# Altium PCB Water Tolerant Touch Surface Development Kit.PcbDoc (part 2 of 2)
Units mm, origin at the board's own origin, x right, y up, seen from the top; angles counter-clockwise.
Board outline 95 x 75 mm, 2 copper layers (Top Layer, Bottom Layer); 89 components, 87 nets, 311 pads, 203 vias.
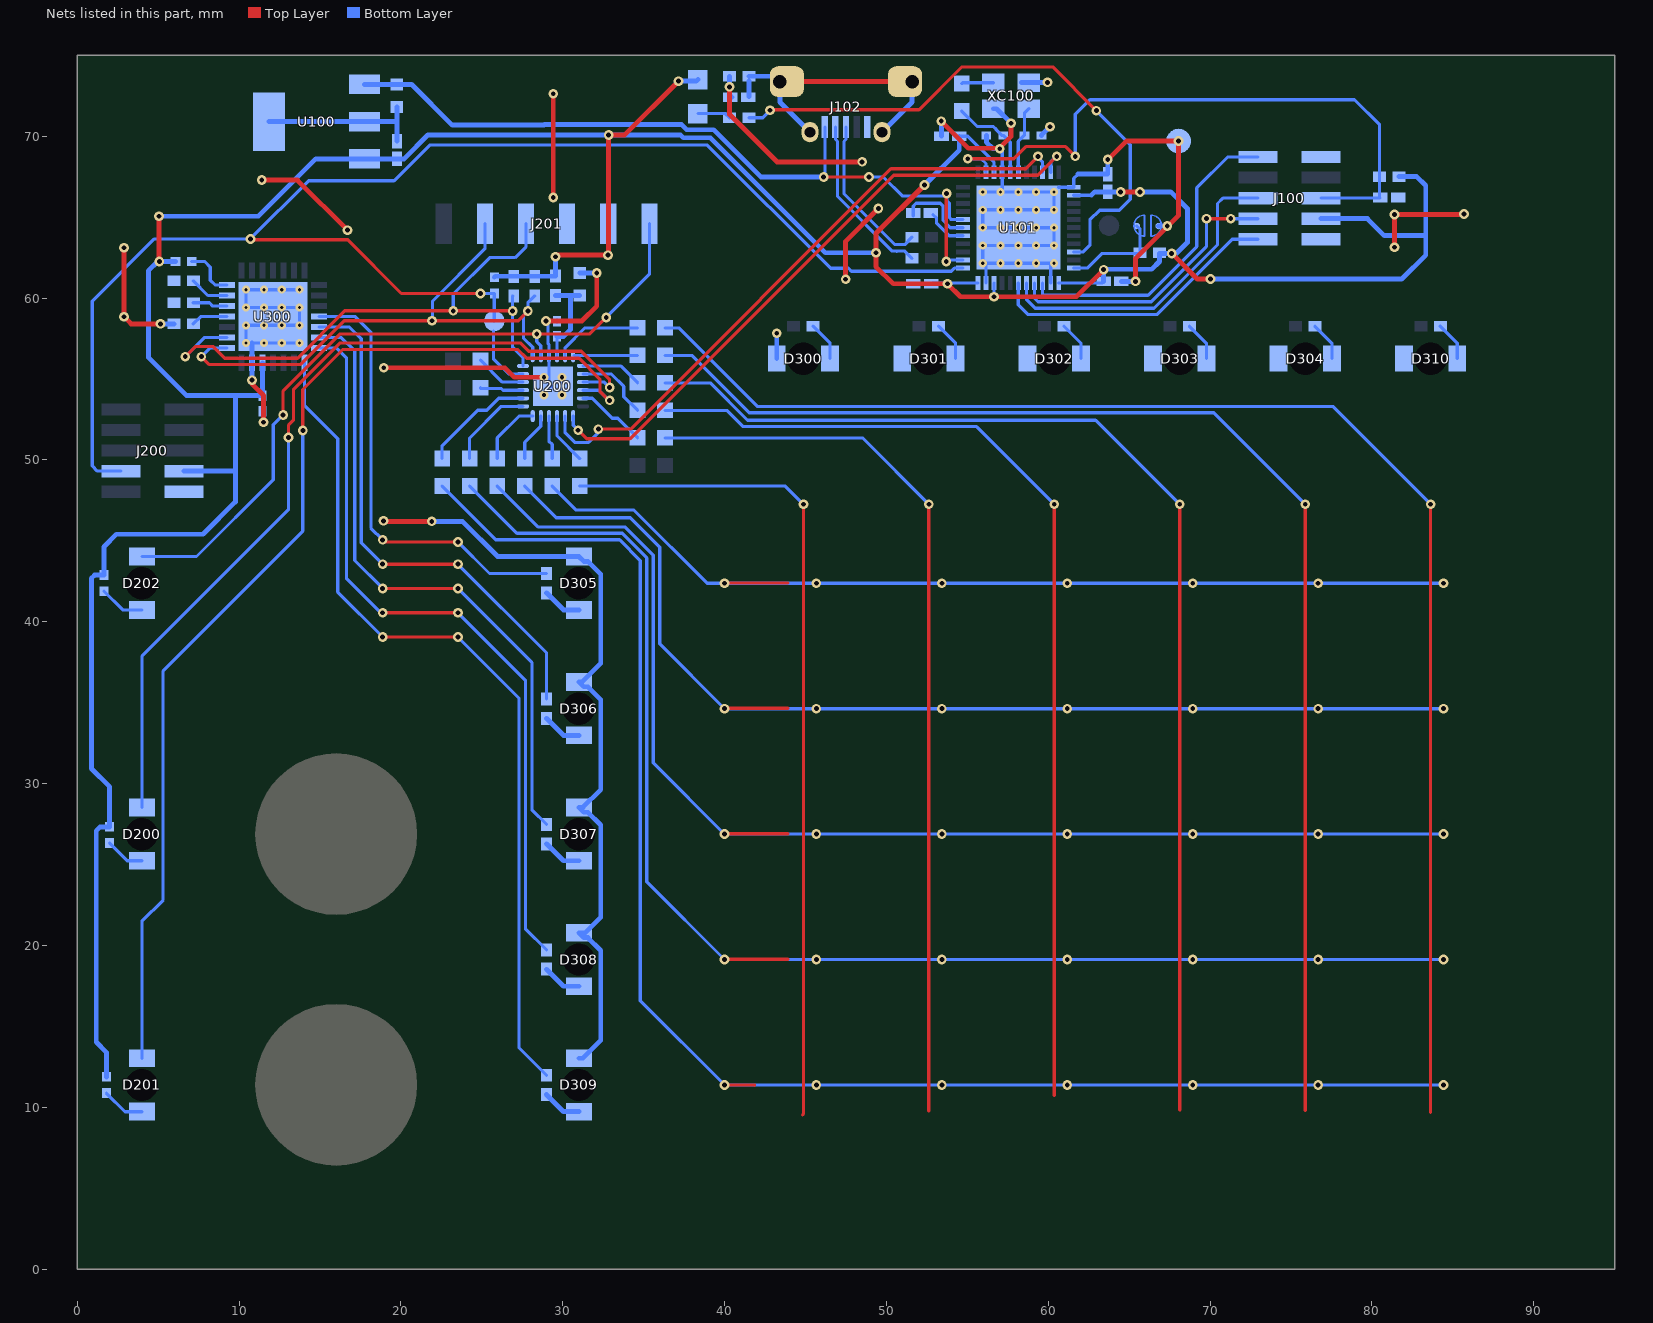
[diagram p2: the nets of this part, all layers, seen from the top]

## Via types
v1: diameter 0.6, hole 0.3, Top Layer to Bottom Layer, 103 vias
v2: diameter 0.6, hole 0.3, Top Layer to Bottom Layer, tented both sides, 55 vias
v3: diameter 0.5, hole 0.2, Top Layer to Bottom Layer, 41 vias
v4: diameter 0.55, hole 0.25, Top Layer to Bottom Layer, 4 vias

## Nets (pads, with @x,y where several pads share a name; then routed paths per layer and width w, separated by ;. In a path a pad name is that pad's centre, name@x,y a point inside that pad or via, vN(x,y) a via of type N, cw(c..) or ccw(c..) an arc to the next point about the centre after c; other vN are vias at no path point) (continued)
GND: C100.2 C101.2 C102.1 C103.1 C104.2 C105.1 C106.1 C107.1 C108.2 C109.1 C110.2 C200.1 C201.1 C300.2 D300.2 D301.2 D302.2 D303.2 D304.2 D305.2 D306.2 D307.2 D308.2 D309.2 D310.2 J100.2 J100.10 J101.1 J102.5 J200.2 J201.3 pad.0 R105.2 R309.1 R311.1 R313.1 U100.2 U100.4 U101.5 U101.15 U101.23 U101.35 U101.43 U101.45 U200.3 U200.25 U300.6 U300.29 XC100.2 XC100.4 | length 216.4
  Top Layer w0.3: v2(2.899,63.105) v2(2.899,58.842) 3.335,58.406 v1(5.15,58.406) ; v1(10.798,54.929) 10.798,54.703 11.516,53.985 v1(11.516,52.325) ; v2(11.403,67.291) 13.611,67.291 v2(16.707,64.195) ; v2(18.929,46.23) 18.96,46.2 v2(21.907,46.2) ; v2(18.941,55.689) 26.43,55.689 27.014,55.105 v4(28.85,55.105) ; v2(28.971,58.58) 31.187,58.58 32.107,59.5 v2(32.107,61.55) ; v2(29.414,66.212) v2(29.414,72.624) ; v2(40.307,73.05) 40.307,71.352 43.243,68.415 v1(48.506,68.415) ; v2(47.485,61.161) 47.485,63.513 v2(49.507,65.534) ; v1(53.391,70.933) 55.068,69.256 56.976,69.256 57.706,69.986 v2(57.706,70.798) ; v1(63.677,68.556) 64.821,69.7 v1(68.057,69.7) 68.057,65.11 65.401,62.455 v1(65.401,61.03) ; v2(81.406,63.142) v2(81.406,65.166) 85.632,65.166 v2@85.693,65.227
  Bottom Layer w0.2: v3(13.74,57.215) 10.795,57.215 v3(10.44,57.215) v3(10.44,58.315) v3(13.74,58.315) v3(13.74,59.415) v3(10.44,59.415) v3(10.44,60.515) v3(13.74,60.515) ; v2(28.971,58.58) C201.1@29.65,58.58 ; v2@29.1,58.355 29.1,57.181 29.15,57.131 U200.3@29.15,56.405 29.15,54.555 U200.25@29.4,54.555 ; D300.2@43.226,56.256 D300.2@43.226,56.256 ; v1(48.506,68.415) v1@48.657,68.565 ; C105.1@52.882,65.15 53.107,64.925 53.107,64.625 53.882,63.85 U101.5@54.732,63.85 ; v3(55.957,66.55) v3(57.057,66.55) ; U101.43@56.157,60.925 U101.45@56.157,62.15 ; v2(57.007,69.225) 57.157,69.075 U101.15@57.157,67.775 57.157,66.65 v3(57.057,66.55) ; U101.35@60.157,60.925 U101.45@60.157,62.15 ; v3(60.357,62.15) v3(55.957,62.15) v3(55.957,63.25) v3(60.357,63.25) v3(60.357,64.35) v3(55.957,64.35) v3(55.957,65.45) v3(60.357,65.45) v3(60.357,66.55) v3(57.057,66.55) ; U101.45@60.657,66.85 U101.23@61.582,66.85 61.582,67.392 61.846,67.656
  Bottom Layer w0.3: v1(5.15,58.406) R309.1@5.977,58.406 ; U300.29@10.795,57.215 10.8,57.21 U300.6@10.8,56.005 10.812,55.993 10.798,55.978 v1(10.798,54.929) ; v3(11.54,58.315) U300.29@11.56,58.315 ; U100.4@11.857,70.9 18.157,70.9 19.707,70.9 19.757,70.85 ; C100.2@19.757,69.7 19.757,70.85 ; C101.2@19.757,71.802 19.757,70.85 ; v2(21.907,46.2) 23.807,46.2 25.977,44.03 D305.2@31,44.03 31.3,43.73 31.559,43.73 32.35,42.939 32.35,37.421 31.207,36.279 D306.2@31,36.279 31.3,35.979 31.559,35.979 32.35,35.188 32.35,29.625 31.253,28.528 D307.2@31,28.528 31.3,28.228 31.559,28.228 32.35,27.437 32.35,21.727 31.4,20.777 D308.2@31,20.777 31.3,20.477 31.559,20.477 32.35,19.686 32.35,14.126 31.25,13.026 D309.2@31,13.026 ; C200.1@31.057,61.548 31.058,61.55 v2(32.107,61.55) ; R105.2@40.307,73.7 v2(40.307,73.05) 40.307,72.555 C106.1@40.457,72.405 ; D300.2@43.226,56.256 v1(43.225,57.826) ; v1(53.391,70.933) 53.407,70.916 C108.2@53.407,70 ; C109.1@56.182,70.05 56.182,69.634 56.591,69.225 v2(57.007,69.225) ; XC100.2@56.607,71.7 56.804,71.7 v2(57.706,70.798) ; XC100.4@58.353,73.325 v1(59.957,73.325) ; C110.2@59.582,70.05 v1(60.112,70.58) ; 61.846,67.656 C107.1@63.677,67.656 v1(63.677,68.556) ; C104.2@64.525,61.03 v1(65.401,61.03) ; J101.1@66.825,64.45 67,64.45 v1(67.357,64.45)
  other v2: 85.693,65.198
  other v3: 11.54,57.215 12.64,57.215 12.64,58.315 11.54,59.415 12.64,59.415 11.54,60.515 12.64,60.515 57.057,62.15 58.157,62.15 59.257,62.15 57.057,63.25 58.157,63.25 59.257,63.25 57.057,64.35 58.157,64.35 59.257,64.35 57.057,65.45 58.157,65.45 59.257,65.45 58.157,66.55 59.257,66.55
  other v4: 28.85,54.005 29.95,54.005 29.95,55.105
NetC105_2: C105.2 U101.6 | length 4.9
  Bottom Layer w0.2: C105.2@51.657,65.075 51.657,65.674 51.833,65.85 53.331,65.85 53.507,65.674 53.507,65.549 53.507,64.791 53.948,64.35 U101.6@54.732,64.35
NetD100_1: D100.1 R101.2 | length 2.1
  Bottom Layer w0.2: D100.1@38.357,71.4 40.052,71.4 R101.2@40.307,71.145
NetD200_1: D200.1 R217.1 | length 2.4
  Bottom Layer w0.2: R217.1@2.007,26.322 3.102,25.227 D200.1@4,25.227
NetD201_1: D201.1 R218.1 | length 2.7
  Bottom Layer w0.2: R218.1@1.807,10.876 2.957,9.726 D201.1@4,9.726
NetD202_1: D202.1 R219.1 | length 2.8
  Bottom Layer w0.2: R219.1@1.657,41.88 2.807,40.73 D202.1@4,40.73
NetD300_1: D300.1 R314.2 | length 2.4
  Bottom Layer w0.2: R314.2@45.476,58.256 46.526,57.206 D300.1@46.526,56.256
NetD301_1: D301.1 R305.2 | length 2.4
  Bottom Layer w0.2: R305.2@53.227,58.256 54.277,57.206 D301.1@54.277,56.256
NetD302_1: D302.1 R304.2 | length 2.4
  Bottom Layer w0.2: R304.2@60.978,58.256 62.028,57.206 D302.1@62.028,56.256
NetD303_1: D303.1 R302.2 | length 2.4
  Bottom Layer w0.2: R302.2@68.729,58.256 69.779,57.206 D303.1@69.779,56.256
NetD304_1: D304.1 R301.2 | length 2.4
  Bottom Layer w0.2: R301.2@76.48,58.256 77.53,57.206 D304.1@77.53,56.256
NetD305_1: D305.1 R306.2 | length 2.4
  Bottom Layer w0.3: R306.2@29,41.78 30.05,40.73 D305.1@31,40.73
NetD306_1: D306.1 R307.2 | length 2.4
  Bottom Layer w0.3: R307.2@29,34.029 30.05,32.979 D306.1@31,32.979
NetD307_1: D307.1 R308.2 | length 2.4
  Bottom Layer w0.3: R308.2@29,26.278 30.05,25.228 D307.1@31,25.228
NetD308_1: D308.1 R310.2 | length 2.4
  Bottom Layer w0.3: R310.2@29,18.527 30.05,17.477 D308.1@31,17.477
NetD309_1: D309.1 R312.2 | length 2.4
  Bottom Layer w0.3: R312.2@29,10.776 30.05,9.726 D309.1@31,9.726
NetD310_1: D310.1 R300.2 | length 2.4
  Bottom Layer w0.2: R300.2@84.231,58.256 85.281,57.206 D310.1@85.281,56.256
NetJ101_2: J101.2 R102.1 U101.33 | length 6.2
  Bottom Layer w0.2: U101.33@61.582,61.85 62.427,61.85 63.333,62.756 R102.1@65.677,62.756 ; J101.2@65.475,64.45 65.677,64.248 65.677,63.885 R102.1@65.677,62.806
NetJ103_1: J103.1 XC100.3 | length 2
  Bottom Layer w0.2: J103.1@54.657,73.25 54.707,73.3 XC100.3@56.607,73.3
NetR303_1: R303.1 U300.14 | length 3.2
  Bottom Layer w0.2: R303.1@7.077,62.256 7.877,62.256 8.227,61.906 8.227,61.106 8.528,60.805 U300.14@9.25,60.805
NetR309_2: R309.2 U300.11 | length 2.3
  Bottom Layer w0.2: R309.2@7.177,58.406 7.626,58.855 U300.11@9.25,58.855
NetR311_2: R311.2 U300.12 | length 2.2
  Bottom Layer w0.2: R311.2@7.177,59.706 8.177,59.706 8.378,59.505 U300.12@9.25,59.505
NetR313_2: R313.2 U300.13 | length 2.4
  Bottom Layer w0.2: R313.2@7.177,61.056 8.078,60.155 U300.13@9.25,60.155
PA0_UPDI_RST: J200.3 R203.1 TP200.1 U101.1 U200.23 | length 95.3
  Top Layer w0.2: v2(10.707,63.65) 10.762,63.595 16.723,63.595 20.037,60.28 v1(24.926,60.28)
  Bottom Layer w0.2: J200.3@2.7,49.305 1.251,49.305 0.925,49.63 0.925,59.804 4.771,63.65 v2(10.707,63.65) 14.307,67.25 19.581,67.25 21.781,69.45 38.939,69.45 46.555,61.834 47.661,61.834 47.839,61.655 54.01,61.655 54.204,61.85 U101.1@54.732,61.85 ; v1(24.926,60.28) R203.1@25.775,60.28 TP200.1@25.775,58.58 ; TP200.1@25.732,57.95 25.732,56.224 26.65,55.305 U200.23@27.55,55.305
PA1_I2C_SDA: J201.4 R202.1 U200.24 U300.9 | length 37.8
  Top Layer w0.2: v1(6.675,56.38) 7.295,57 8.407,57 9.12,56.286 13.619,56.286 16.54,59.207 v2(23.241,59.207) 26.899,59.207 v1(26.907,59.2)
  Bottom Layer w0.2: v1(6.675,56.38) 7.85,57.555 U300.9@9.25,57.555 ; v2(23.241,59.207) 23.241,60.249 25.492,62.5 27.057,62.5 27.737,63.18 J201.4@27.737,64.6 ; R202.1@26.925,60.13 26.907,60.112 v1(26.907,59.2) 26.907,56.949 27.55,56.305 U200.24@27.55,55.805
PA2_I2C_SCL: J201.5 R201.1 U200.1 U300.8 | length 35.4
  Top Layer w0.2: v1(7.675,56.38) 8.169,55.886 13.784,55.886 16.498,58.6 27.256,58.6 v1(27.85,59.195)
  Bottom Layer w0.2: v1(7.675,56.38) 8.2,56.905 U300.8@9.25,56.905 ; v2(21.92,58.6) 21.92,58.713 v2@21.957,58.75 ; v2@21.957,58.55 v2@21.957,58.75 ; J201.5@25.197,64.6 25.197,63.04 21.957,59.8 v2@21.957,58.75 ; U200.1@28.15,56.405 28.15,56.957 27.575,57.532 27.575,58.92 v1(27.85,59.195) 27.85,59.705 R201.1@28.275,60.13
PA3_STATUS_LED_3: D202.2 J201.1 U200.2 | length 46.1
  Top Layer w0.2: v1(12.725,52.775) 12.725,54.261 16.244,57.78 v1(28.399,57.78) 31.673,57.78 v2(32.695,58.802)
  Bottom Layer w0.2: D202.2@4,44.03 7.375,44.03 12.116,48.771 12.116,52.166 v1(12.725,52.775) ; v1(28.399,57.78) 28.399,57.311 28.65,57.059 U200.2@28.65,56.405 ; v2(32.695,58.802) 35.357,61.464 J201.1@35.357,64.6
PB2_UART_TX: U101.20 U200.14 | length 39.1
  Top Layer w0.2: v1(32.207,51.9) 34.198,51.9 50.284,67.986 58.607,67.986 v1(59.377,68.756)
  Bottom Layer w0.2: U200.14@30.15,52.705 30.15,51.676 30.749,51.077 31.599,51.077 32.207,51.685 v1(32.207,51.9) ; v1(59.377,68.756) 59.377,68.682 59.375,68.68 59.657,68.399 U101.20@59.657,67.775
PB3_UART_RX: U101.21 U200.13 | length 39.7
  Top Layer w0.2: v1(30.958,51.83) 31.488,51.3 34.164,51.3 50.449,67.586 59.357,67.586 v1(60.527,68.756)
  Bottom Layer w0.2: 30.657,52.15 30.657,52.699 U200.13@30.65,52.705 30.65,52.137 v1(30.958,51.83) ; U101.21@60.157,67.775 60.157,68.413 60.5,68.756 v1(60.527,68.756)
PB6_LED_2: D201.2 U200.10 | length 69.1
  Top Layer w0.2: v1(13.945,51.816) 13.945,54.349 16.415,56.82 27.229,56.82 27.773,56.276 31.015,56.276 32.3,54.99 32.3,54.229 32.852,53.677 v1(32.9,53.677)
  Bottom Layer w0.2: D201.2@4,13.026 4,21.493 5.307,22.8 5.307,36.962 13.945,45.599 v1(13.945,51.816) ; U200.10@31.25,54.305 32.224,54.305 32.852,53.677 v1(32.9,53.677)
PB7_LED_1: D200.2 U200.9 | length 53.6
  Top Layer w0.2: v1(13.056,51.384) 13.056,52.131 13.36,52.436 13.36,54.331 16.256,57.226 27.388,57.226 27.909,56.705 31.15,56.705 32.9,54.955 v1(32.9,54.477)
  Bottom Layer w0.2: D200.2@4,28.527 4,37.855 13.056,46.91 v1(13.056,51.384) ; U200.9@31.25,54.805 32.572,54.805 v1(32.9,54.477)
ROW_1: R306.1 U300.25 | length 27.7
  Top Layer w0.2: v1(18.877,45.056) 19.003,44.93 v1(23.527,44.93)
  Bottom Layer w0.2: U300.25@14.95,58.855 17.178,58.855 18.15,57.883 18.15,45.783 v1(18.877,45.056) ; v1(23.527,44.93) 25.477,42.98 R306.1@29,42.98
ROW_2: R307.1 U300.26 | length 32.6
  Top Layer w0.2: v1(18.877,43.556) v1(23.527,43.556)
  Bottom Layer w0.2: U300.26@14.95,58.205 16.828,58.205 17.55,57.483 17.55,44.883 v1(18.877,43.556) ; v1(23.527,43.556) 29,38.083 R307.1@29,35.229
ROW_3: R308.1 U300.27 | length 39.4
  Top Layer w0.2: v1(18.877,42.056) v1(23.527,42.056)
  Bottom Layer w0.2: U300.27@14.95,57.555 16.328,57.555 17.15,56.733 17.15,43.783 v1(18.877,42.056) ; v1(23.527,42.056) 28.1,37.483 28.1,28.378 R308.1@29,27.478
ROW_4: R310.1 U300.28 | length 46.4
  Top Layer w0.2: v1(18.877,40.556) v1(23.527,40.556)
  Bottom Layer w0.2: U300.28@14.95,56.905 16.028,56.905 16.65,56.283 16.65,42.657 18.751,40.556 v1(18.877,40.556) ; v1(23.527,40.556) 27.7,36.383 27.7,21.027 R310.1@29,19.727
ROW_5: R312.1 U300.1 | length 52.9
  Top Layer w0.2: v1(18.877,39.056) v1(23.527,39.056)
  Bottom Layer w0.2: U300.1@14.05,56.005 14.05,53.356 16.1,51.306 16.1,41.833 v1(18.877,39.056) ; v1(23.527,39.056) 27.3,35.283 27.3,13.676 R312.1@29,11.976
S\R\S\T\: C102.2 J100.6 R100.1 U101.13 | length 39.6
  Top Layer w0.2: v1(55.027,68.606) 57.877,68.606 58.627,69.356 61.077,69.356 v1(61.677,68.756)
  Bottom Layer w0.2: v1(55.027,68.606) 55.865,68.606 56.157,68.314 U101.13@56.157,67.775 U101.13@56.107,67.825 ; v1(61.677,68.756) 61.677,71.356 62.577,72.256 78.927,72.256 80.477,70.706 R100.1@80.477,67.506 C102.2@80.477,66.256 ; J100.6@76.857,66.175 C102.2@80.496,66.175
SHIELD: C106.2 J102.6@43.419,73.375 J102.7@51.594,73.375 J102.8@45.282,70.25 J102.9@49.732,70.25 R105.1 | length 19.3
  Top Layer w0.3: J102.6@43.419,73.375 J102.7@51.594,73.375
  Bottom Layer w0.3: C106.2@41.507,72.455 R105.1@41.507,73.425 ; R105.1@41.507,73.7 43.094,73.7 J102.6@43.419,73.375 ; J102.6@43.169,73.125 J102.6@43.419,73.375 ; J102.8@45.282,70.25 43.419,72.112 J102.6@43.419,73.375 ; J102.9@49.732,70.25 51.594,72.112 J102.7@51.594,73.375
STATUS_LED: R101.1 U101.31 | length 36
  Top Layer w0.2: v2@42.807,71.63 52.025,71.63 54.675,74.28 60.275,74.28 v1(62.977,71.579)
  Bottom Layer w0.2: R101.1@41.507,71.145 42.371,71.145 42.807,71.58 v2(42.807,71.6) ; U101.31@61.582,62.85 62.171,62.85 62.577,63.256 62.577,64.832 63.175,65.43 64.401,65.43 65.077,66.106 65.077,69.479 v1(62.977,71.579)
TCK: J100.1 U101.39 | length 18.3
  Bottom Layer w0.2: U101.39@58.157,60.925 58.157,59.575 58.757,58.975 66.706,58.975 71.366,63.635 J100.1@72.957,63.635
TDI: J100.9 U101.36 | length 19.7
  Bottom Layer w0.2: U101.36@59.657,60.925 59.657,60.225 59.707,60.175 66.174,60.175 69.178,63.178 69.178,66.807 71.086,68.715 J100.9@72.957,68.715
TDO: J100.3 U101.37 | length 18
  Top Layer w0.2: v1(69.778,64.905) v1(71.278,64.905)
  Bottom Layer w0.2: U101.37@59.157,60.925 59.157,59.991 59.373,59.775 66.374,59.775 69.778,63.178 v1(69.778,64.905) ; v1(71.278,64.905) J100.3@72.957,64.905
TMS: J100.5 U101.38 | length 19.8
  Bottom Layer w0.2: U101.38@58.657,60.925 58.657,59.925 59.207,59.375 66.54,59.375 70.461,63.296 70.461,65.84 70.796,66.175 J100.5@72.957,66.175
USB_VBUS: C101.1 J102.1 U100.1 U101.2 U101.7 | length 49.8
  Top Layer w0.2: v1(46.125,67.476) v1(48.925,67.476) ; v2(53.7,62.255) 53.7,66.429 v1(53.727,66.456)
  Bottom Layer w0.2: v1(46.125,67.476) 46.207,67.557 J102.1@46.207,70.575 ; v1(48.925,67.476) 49.825,67.476 51.001,66.3 53.571,66.3 v1(53.727,66.456) 53.727,66.02 53.907,65.84 53.907,64.956 54.013,64.85 U101.7@54.732,64.85 ; v2(53.7,62.255) 53.794,62.35 U101.2@54.732,62.35
  Bottom Layer w0.3: U100.1@17.757,73.2 17.758,73.198 C101.1@19.757,73.198 20.658,73.198 23.173,70.684 28.838,70.684 28.882,70.729 37.333,70.729 37.662,70.4 39.333,70.4 42.257,67.476 v1(46.125,67.476)
USBD_N: J102.2 R103.1 | length 10.7
  Bottom Layer w0.2: J102.2@46.857,70.575 46.857,69.8 46.982,69.675 46.982,66.285 50.367,62.9 50.641,62.9 50.649,62.892 ; 50.438,62.9 51.132,62.9 R103.1@51.582,62.45
USBD_P: J102.3 R104.1 | length 9.9
  Bottom Layer w0.2: J102.3@47.507,70.575 47.507,69.8 47.382,69.675 47.382,66.451 50.533,63.3 51.132,63.3 R104.1@51.582,63.75
VCC_MCU_P3V3: C200.2 C201.2 R200.2 U200.4 | length 5.8
  Bottom Layer w0.2: U200.4@29.65,56.405 C201.2@29.65,57.63
  Bottom Layer w0.3: R200.2@29.557,60.15 29.558,60.152 30.515,60.152 ; C201.2@29.65,57.63 30.063,57.63 30.475,58.043 30.475,60.112 30.515,60.152 ; C200.2@31.057,60.152 30.515,60.152
VCC_TARGET_P3V3: C100.1 C103.2 C104.1 C107.2 C108.1 C300.1 D100.2 J100.4 J200.4 J201.2 R100.2 R102.2 R200.1 R201.2 R202.2 R203.2 R217.2 R218.2 R219.2 R303.2 U100.3 U101.14 U101.24 U101.34 U101.42 U101.44 U300.5 | length 230.2
  Top Layer w0.3: v1(5.057,65.05) 5.057,62.276 v1(5.077,62.256) ; v2(29.557,62.55) 29.657,62.65 v2(32.807,62.65) 32.842,62.685 v2(32.842,70.079) 33.835,70.079 v2(37.157,73.4) ; v1(52.357,66.986) 49.357,63.986 v1(49.357,62.8) 49.357,61.946 50.422,60.88 v1(53.775,60.88) 54.581,60.075 v1(56.657,60.075) 61.746,60.075 v1(63.425,61.754) ; v1(64.477,66.556) v1(65.677,66.556) ; v1(67.627,62.756) 69.207,61.176 v1(70.025,61.176)
  Bottom Layer w0.2: v1(53.775,60.88) 53.82,60.925 U101.44@55.657,60.925 ; C108.1@54.507,70 55.036,70 56.657,68.379 U101.14@56.657,67.775 ; v1(56.657,60.075) U101.42@56.657,60.925 ; U101.34@60.657,60.925 63.32,60.925 C104.1@63.425,61.03 ; U101.24@61.582,66.35 62.671,66.35
  Bottom Layer w0.3: R218.2@1.807,11.876 1.807,13.399 1.175,14.03 1.175,27.08 1.417,27.322 R217.2@2.007,27.322 2.007,29.799 0.875,30.93 0.875,42.68 1.075,42.88 R219.2@1.657,42.88 1.657,44.636 2.427,45.406 7.777,45.406 9.777,47.406 9.777,49.276 ; v1(5.057,65.05) 11.2,65.05 14.75,68.6 U100.3@17.757,68.6 20.201,68.6 21.679,70.079 37.276,70.079 37.455,69.9 39.126,69.9 46.226,62.8 v1(49.357,62.8) ; R303.2@6.077,62.256 v1(5.077,62.256) 4.977,62.256 4.4,61.679 4.4,56.333 6.752,53.981 9.777,53.981 ; J200.4@6.6,49.305 9.748,49.305 9.777,49.276 ; U300.5@11.45,56.005 11.462,55.992 11.462,54.88 11.45,54.868 11.45,53.981 9.777,53.981 ; R203.2@25.775,61.28 25.845,61.35 R200.1@29.557,61.35 v2(29.557,62.55) ; v2(32.807,62.65) 32.817,62.66 J201.2@32.817,64.6 ; v2(37.157,73.4) 38.257,73.4 D100.2@38.357,73.5 ; v1(52.357,66.986) 54.507,69.136 C108.1@54.507,70 ; C103.2@52.876,60.88 v1(53.775,60.88) ; 62.671,66.35 62.877,66.556 C107.2@63.677,66.556 v1(64.477,66.556) ; C104.1@63.425,61.03 v1(63.425,61.754) 63.451,61.78 66.401,61.78 66.877,62.256 66.877,62.756 v1(67.627,62.756) 67.927,62.756 68.607,63.436 68.607,65.526 67.577,66.556 v1(65.677,66.556) ; v1(70.025,61.176) 81.847,61.176 83.327,62.656 83.327,63.856 ; J100.4@76.857,64.905 79.728,64.905 80.777,63.856 83.327,63.856 ; R100.2@81.677,67.506 82.777,67.506 83.327,66.956 83.327,63.856 ; 9.777,49.276 9.777,53.981
XTAL1: C110.1 U101.17 XC100.1 | length 4.2
  Bottom Layer w0.2: U101.17@58.157,67.775 58.157,69.675 C110.1@58.532,70.05 58.532,71.425 XC100.1@58.807,71.7
XTAL2: C109.2 J103.2 U101.16 | length 5.7
  Bottom Layer w0.2: J103.2@54.657,71.55 55.607,70.6 56.606,70.6 56.782,70.424 56.782,70.401 57.132,70.05 C109.2@57.232,70.05 57.657,69.625 U101.16@57.657,67.775
Y0: R204.1 U200.5 | length 5.5
  Bottom Layer w0.2: U200.5@30.15,56.405 30.15,56.927 31.378,58.155 R204.1@34.625,58.155
Y0_COL6: R204.2 | length 89.4
  Top Layer w0.2: 83.631,9.688 v1(83.631,47.255) v1@83.65,47.236
  Bottom Layer w0.2: R204.2@36.325,58.155 37.17,58.155 42.02,53.305 77.581,53.305 v1(83.631,47.255)
Y1: R210.1 U200.6 | length 3.9
  Bottom Layer w0.2: U200.6@30.7,56.455 R210.1@34.625,56.455
Y1_COL5: R210.2 | length 80.8
  Top Layer w0.2: 75.88,9.811 v1(75.88,47.255)
  Bottom Layer w0.2: R210.2@36.325,56.455 37.985,56.455 41.535,52.905 70.23,52.905 v1(75.88,47.255)
Y2: R211.1 U200.7 | length 3.8
  Bottom Layer w0.2: U200.7@31.25,55.805 33.575,55.805 R211.1@34.625,54.755
Y2_COL4: R211.2 | length 72.3
  Top Layer w0.2: 68.125,9.826 68.129,9.83 v1(68.129,47.255)
  Bottom Layer w0.2: R211.2@36.325,54.755 39.119,54.755 41.419,52.455 62.929,52.455 v1(68.129,47.255)
Y3: R212.1 U200.8 | length 4.7
  Bottom Layer w0.2: U200.8@31.25,55.305 33.01,55.305 33.777,54.539 33.777,54.38 33.777,54.063 33.777,53.904 R212.1@34.625,53.055
Y3_COL3: R212.2 | length 63
  Top Layer w0.2: 60.375,10.726 v1@60.375,47.255
  Bottom Layer w0.2: R212.2@36.325,53.055 40.145,53.055 41.145,52.055 55.578,52.055 v1(60.378,47.255)
Y4: R214.1 U200.15 | length 3.2
  Bottom Layer w0.2: U200.15@29.65,52.705 29.65,51.48 R214.1@31.05,50.08
Y4_COL1: R214.2 | length 52
  Top Layer w0.2: 44.825,9.526 44.876,9.577 v1(44.876,47.255)
  Bottom Layer w0.2: R214.2@31.05,48.38 43.751,48.38 v1(44.876,47.255)
Y5: R209.1 U200.16 | length 2.7
  Bottom Layer w0.2: U200.16@29.15,52.705 29.15,51.156 29.35,50.956 R209.1@29.35,50.08
Y5_ROW5: R209.2 | length 61.4
  Top Layer w0.2: v1@40.019,42.399 43.901,42.399
  Bottom Layer w0.2: R209.2@29.35,48.38 30.83,46.9 34.406,46.9 38.926,42.38 v1(40,42.38) v1(84.432,42.38)
  other v1: 45.677,42.38 53.428,42.38 61.179,42.38 68.93,42.38 76.681,42.38
Y6: R208.1 U200.17 | length 3
  Bottom Layer w0.2: R208.1@27.65,50.08 27.65,51.08 28.65,52.08 U200.17@28.65,52.705
Y6_ROW4: R208.2 | length 69.9
  Top Layer w0.2: v1@40.019,34.648 43.901,34.648
  Bottom Layer w0.2: R208.2@27.65,48.38 29.6,46.43 34.175,46.43 36,44.605 36,38.629 v1(40,34.629) v1(84.432,34.629)
  other v1: 45.677,34.629 53.428,34.629 61.179,34.629 68.93,34.629 76.681,34.629
Y7: R207.1 U200.18 | length 4
  Bottom Layer w0.2: R207.1@25.95,50.08 25.95,51.355 27.3,52.705 U200.18@28.15,52.705
Y7_ROW3: R207.2 | length 78.8
  Top Layer w0.2: v1@40.019,26.897 43.901,26.897
  Bottom Layer w0.2: R207.2@25.95,48.38 28.472,45.859 33.847,45.859 35.6,44.105 35.6,31.278 v1(40,26.878) v1(45.677,26.878) v1(53.428,26.878) v1(61.179,26.878) v1(68.93,26.878) v1(76.681,26.878) v1(84.432,26.878)
Y8: R206.1 U200.19 | length 5.4
  Bottom Layer w0.2: R206.1@24.25,50.08 24.25,51.351 26.205,53.305 U200.19@27.55,53.305
Y8_ROW2: R206.2 | length 87.9
  Top Layer w0.2: v1@40.019,19.146 43.901,19.146
  Bottom Layer w0.2: R206.2@24.25,48.38 27.172,45.459 33.681,45.459 35.2,43.94 35.2,23.927 v1(40,19.127) v1(84.432,19.127)
  other v1: 45.677,19.127 53.428,19.127 61.179,19.127 68.93,19.127 76.681,19.127
Y9: R205.1 U200.20 | length 7
  Bottom Layer w0.2: R205.1@22.55,50.08 22.55,50.871 24.745,53.066 25.31,53.066 26.05,53.805 U200.20@27.55,53.805
Y9_ROW1: R205.2 | length 95
  Top Layer w0.2: v1(40,11.376) 41.831,11.376 41.857,11.35
  Bottom Layer w0.2: R205.2@22.55,48.38 25.872,45.059 33.516,45.059 34.8,43.774 34.8,16.576 v1(40,11.376) v1(45.677,11.376) v1(53.428,11.376) v1(61.179,11.376) v1(68.93,11.376) v1(76.681,11.376) v1(84.432,11.376)
Y10: R215.1 U200.21 | length 2.7
  Bottom Layer w0.2: R215.1@24.925,54.455 24.925,54.405 26.218,54.405 26.318,54.305 U200.21@27.55,54.305
Y11: R216.1 U200.22 | length 3.2
  Bottom Layer w0.2: R216.1@24.925,56.155 26.275,54.805 U200.22@27.55,54.805
Y12: R213.1 U200.11 | length 4.4
  Bottom Layer w0.2: U200.11@31.25,53.805 31.837,53.805 33.065,52.577 33.403,52.577 R213.1@34.625,51.355
Y12_COL2: R213.2 | length 55.5
  Top Layer w0.2: v1(52.627,47.255) 52.625,9.776 52.627,9.778 ; v1(52.627,47.255) v1@52.627,47.296
  Bottom Layer w0.2: R213.2@36.325,51.355 48.527,51.355 v1(52.627,47.255)
pads on no net: D200.0 D201.0 D202.0 D300.0 D301.0 D302.0 D303.0 D304.0 D305.0 D306.0 D307.0 D308.0 D309.0 D310.0 J100.7 J100.8 J102.4 J102.6@43.907,73.375 J102.7@51.107,73.375 J102.8@45.282,70.25 J102.9@49.732,70.25 J200.1 J200.5 J200.6 J200.7 J200.8 J200.9 J200.10 J201.6 U101.8 U101.9 U101.10 U101.11 U101.12 U101.18 U101.19 U101.22 U101.25 U101.26 U101.27 U101.28 U101.29 U101.30 U101.40 U101.41 U300.2 U300.3 U300.4 U300.7 U300.10 U300.15 U300.16 U300.23 U300.24

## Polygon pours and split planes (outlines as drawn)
DRIVEN_SHIELD on Top Layer "DS" (solid, remove dead copper, pour order 12): 2.362,3 92,3 92,57.855 2.362,57.855
DRIVEN_SHIELD on Bottom Layer "DS" (solid, remove dead copper, pour order 14): 5.207,3 92,3 92,50.267 32.156,50.267 32.156,37.836 5.207,37.836
GND on Bottom Layer "Top Layer" (solid, remove dead copper, pour order 10): 19.257,45.6 18.757,45.6 2.184,45.6 2.184,74.15 92,74.15 92,54.839 41.518,54.839 36.857,59.5 35.207,59.5 32.507,59.5 19.257,59.5

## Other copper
Top Layer:
  pour cut-out: 2.172,57.757 2.172,45.555 32.042,45.555 32.332,45.555 32.332,57.757
  pour cut-out: 40.757,7.25 87.757,7.25 87.757,46.5 40.757,46.5
  pour cut-out: 29.85,24.478 29.85,29.278 32.15,29.278 32.15,24.478
  pour cut-out: 29.65,39.78 32.35,39.78 32.35,44.98 29.65,44.98
  pour cut-out: 29.65,32.029 32.35,32.029 32.35,37.229 29.65,37.229
  pour cut-out: 29.65,16.527 32.35,16.527 32.35,21.727 29.65,21.727
  pour cut-out: 29.65,8.776 32.35,8.776 32.35,13.976 29.65,13.976
  region net Y9_ROW1: 52.287,11.376 48.752,14.911 45.216,11.376 48.752,7.84
  region net Y4_COL1: 44.876,18.787 41.34,15.251 44.876,11.716 48.412,15.251
  region net Y4_COL1: 44.876,11.036 48.412,7.5 41.34,7.5
  region net Y9_ROW1: 44.536,11.376 41,7.84 41,14.911
  region net Y12_COL2: 52.627,11.036 56.163,7.5 49.092,7.5
  region net Y12_COL2: 52.627,18.787 49.092,15.251 52.627,11.716 56.163,15.251
  region net Y9_ROW1: 60.038,11.376 56.503,14.911 52.967,11.376 56.503,7.84
  region net Y3_COL3: 60.378,11.036 63.914,7.5 56.843,7.5
  region net Y3_COL3: 60.378,18.787 56.843,15.251 60.378,11.716 63.914,15.251
  region net Y9_ROW1: 67.789,11.376 64.254,14.911 60.718,11.376 64.254,7.84
  region net Y0_COL6: 83.631,18.787 80.096,15.251 83.631,11.716 87.167,15.251
  region net Y0_COL6: 83.631,11.036 87.167,7.5 80.096,7.5
  region net Y9_ROW1: 83.291,11.376 79.756,14.911 76.22,11.376 79.756,7.84
  region net Y1_COL5: 75.88,18.787 72.345,15.251 75.88,11.716 79.416,15.251
  region net Y1_COL5: 75.88,11.036 79.416,7.5 72.345,7.5
  region net Y2_COL4: 68.129,11.036 71.665,7.5 64.594,7.5
  region net Y2_COL4: 68.129,18.787 64.594,15.251 68.129,11.716 71.665,15.251
  region net Y9_ROW1: 75.54,11.376 72.005,14.911 68.469,11.376 72.005,7.84
  region net Y9_ROW1: 83.971,11.376 87.507,14.911 87.507,7.84
  region net Y8_ROW2: 83.971,19.127 87.507,22.662 87.507,15.591
  region net Y8_ROW2: 75.54,19.127 72.005,22.662 68.469,19.127 72.005,15.591
  region net Y2_COL4: 68.129,26.538 64.594,23.002 68.129,19.467 71.665,23.002
  region net Y1_COL5: 75.88,26.538 72.345,23.002 75.88,19.467 79.416,23.002
  region net Y8_ROW2: 83.291,19.127 79.756,22.662 76.22,19.127 79.756,15.591
  region net Y0_COL6: 83.631,26.538 80.096,23.002 83.631,19.467 87.167,23.002
  region net Y8_ROW2: 67.789,19.127 64.254,22.662 60.718,19.127 64.254,15.591
  region net Y3_COL3: 60.378,26.538 56.843,23.002 60.378,19.467 63.914,23.002
  region net Y8_ROW2: 60.038,19.127 56.503,22.662 52.967,19.127 56.503,15.591
  region net Y12_COL2: 52.627,26.538 49.092,23.002 52.627,19.467 56.163,23.002
  region net Y8_ROW2: 44.536,19.127 41,15.591 41,22.662
  region net Y4_COL1: 44.876,26.538 41.34,23.002 44.876,19.467 48.412,23.002
  region net Y8_ROW2: 52.287,19.127 48.752,22.662 45.216,19.127 48.752,15.591
  region net Y7_ROW3: 83.971,26.878 87.507,30.413 87.507,23.342
  region net Y7_ROW3: 75.54,26.878 72.005,30.413 68.469,26.878 72.005,23.342
  region net Y2_COL4: 68.129,34.289 64.594,30.753 68.129,27.218 71.665,30.753
  region net Y1_COL5: 75.88,34.289 72.345,30.753 75.88,27.218 79.416,30.753
  region net Y7_ROW3: 83.291,26.878 79.756,30.413 76.22,26.878 79.756,23.342
  region net Y0_COL6: 83.631,34.289 80.096,30.753 83.631,27.218 87.167,30.753
  region net Y7_ROW3: 67.789,26.878 64.254,30.413 60.718,26.878 64.254,23.342
  region net Y3_COL3: 60.378,34.289 56.843,30.753 60.378,27.218 63.914,30.753
  region net Y7_ROW3: 60.038,26.878 56.503,30.413 52.967,26.878 56.503,23.342
  region net Y12_COL2: 52.627,34.289 49.092,30.753 52.627,27.218 56.163,30.753
  region net Y7_ROW3: 44.536,26.878 41,23.342 41,30.413
  region net Y4_COL1: 44.876,34.289 41.34,30.753 44.876,27.218 48.412,30.753
  region net Y7_ROW3: 52.287,26.878 48.752,30.413 45.216,26.878 48.752,23.342
  region net Y6_ROW4: 83.971,34.629 87.507,38.164 87.507,31.093
  region net Y6_ROW4: 75.54,34.629 72.005,38.164 68.469,34.629 72.005,31.093
  region net Y2_COL4: 68.129,42.04 64.594,38.504 68.129,34.969 71.665,38.504
  region net Y1_COL5: 75.88,42.04 72.345,38.504 75.88,34.969 79.416,38.504
  region net Y6_ROW4: 83.291,34.629 79.756,38.164 76.22,34.629 79.756,31.093
  region net Y0_COL6: 83.631,42.04 80.096,38.504 83.631,34.969 87.167,38.504
  region net Y6_ROW4: 67.789,34.629 64.254,38.164 60.718,34.629 64.254,31.093
  region net Y3_COL3: 60.378,42.04 56.843,38.504 60.378,34.969 63.914,38.504
  region net Y6_ROW4: 60.038,34.629 56.503,38.164 52.967,34.629 56.503,31.093
  region net Y12_COL2: 52.627,42.04 49.092,38.504 52.627,34.969 56.163,38.504
  region net Y6_ROW4: 44.536,34.629 41,31.093 41,38.164
  region net Y4_COL1: 44.876,42.04 41.34,38.504 44.876,34.969 48.412,38.504
  region net Y6_ROW4: 52.287,34.629 48.752,38.164 45.216,34.629 48.752,31.093
  region net Y5_ROW5: 83.971,42.38 87.507,45.915 87.507,38.844
  region net Y5_ROW5: 75.54,42.38 72.005,45.915 68.469,42.38 72.005,38.844
  region net Y5_ROW5: 83.291,42.38 79.756,45.915 76.22,42.38 79.756,38.844
  region net Y5_ROW5: 67.789,42.38 64.254,45.915 60.718,42.38 64.254,38.844
  region net Y5_ROW5: 60.038,42.38 56.503,45.915 52.967,42.38 56.503,38.844
  region net Y5_ROW5: 44.536,42.38 41,38.844 41,45.915
  region net Y5_ROW5: 52.287,42.38 48.752,45.915 45.216,42.38 48.752,38.844
  region net Y4_COL1: 44.876,42.72 41.34,46.255 48.412,46.255
  region net Y12_COL2: 52.627,42.72 49.092,46.255 56.163,46.255
  region net Y3_COL3: 60.378,42.72 56.843,46.255 63.914,46.255
  region net Y2_COL4: 68.129,42.72 64.594,46.255 71.665,46.255
  region net Y1_COL5: 75.88,42.72 72.345,46.255 79.416,46.255
  region net Y0_COL6: 83.631,42.72 80.096,46.255 87.167,46.255
Bottom Layer:
  rectangle net GND: 28.175,53.33 30.625,55.78
  pour cut-out: 28.225,39.779 32.35,39.779 32.35,44.979 28.225,44.979
  pour cut-out: 28.225,32.029 32.35,32.029 32.35,37.229 28.225,37.229
  pour cut-out: 28.225,24.277 32.35,24.277 32.35,29.477 28.225,29.477
  pour cut-out: 28.225,16.526 32.35,16.526 32.35,21.726 28.225,21.726
  pour cut-out: 28.225,8.776 32.35,8.776 32.35,13.976 28.225,13.976

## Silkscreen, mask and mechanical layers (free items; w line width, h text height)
Bottom Overlay:
  lines w0.3: 4.564,55.138 4.564,62.852 4.563,62.852 4.563,64.356 20.832,64.356 ; 7.827,45.472 28.235,45.472 41.62,45.472 41.62,59.385 48.582,59.385 83.431,59.385 83.431,74.397 53.231,74.397 ; 8.482,54.587 12.649,54.587 20.846,54.587 20.846,59.177 20.846,62.535 ; 36.644,74.371 20.846,74.371 20.846,62.535 ; 38,66.807 37.308,67.499 ; 38.031,68.222 37.308,67.499 ; 41.59,62.504 41.622,62.504 41.622,58.363 41.62,58.363 ; 41.622,62.535 20.846,62.535 ; 41.679,65.611 41.679,67.499 37.308,67.499
  text "DEBUG" at 82.757,71.747 h3
  text "GND" at 69.507,70.85 h1.52
  text "STATUS" at 42.457,69.103 h1.5
  text "mEDBG" at 66.624,68.912 h1.8
  text "DEBUG /  USB" at 50.354,66.615 h1.8
  text "1" at 37.238,65.382 h1.52
  text "LED / DRIVER" at 20.415,64.272 h2.8 r90
  text "KRONOCOMM" at 47.767,63.904 h1.8
  text "MCP23017" at 8.856,63.735 h1.52 r180
  text "TOUCH" at 41.26,60.18 h3
  text "ATTINY1617" at 27.61,51.105 h1.52
  text "UPDI DEBUG" at 18.528,47.925 h1.8
  text "M" at 71.265,38.786 h10
  text "Water Tolerant Touch Surface Development Kit" at 82.11,31.445 h3
  text "Microchip © 2018" at 72.75,6.85 h2.5
  text "A08-2769  Rev 3" at 69.442,3.589 h2
  text "p" at 39.15,1.15 h8
  text "e" at 30.95,1.1 h8
  text "c" at 48.75,1.1 h7.5
  text "" at 20.25,-1.45 h12
Mechanical 1:
  the board outline again, w0.254
Mechanical 4:
  circle w0.254: c16,26.877 r5
  circle w0.254: c16,11.38 r5
  circle w0.254: c4,42.38 r1
  circle w0.254: c4,26.877 r1
  circle w0.254: c4,11.376 r1
  circle w0.254: c83.631,56.256 r1
  circle w0.254: c75.88,56.256 r1
  circle w0.254: c68.125,56.256 r1
  circle w0.254: c60.378,56.256 r1
  circle w0.254: c52.627,56.256 r1
  circle w0.254: c44.876,56.256 r1
  circle w0.254: c31,42.38 r1
  circle w0.254: c31,34.629 r1
  circle w0.254: c31,26.878 r1
  circle w0.254: c31,19.127 r1
  circle w0.254: c31,11.376 r1
  text "ALL DIMENSIONS ARE IN MM" at 5.4,-13.25 h3

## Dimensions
44.876,56.256 to 0,75 on Mechanical 4
44.876,56.256 to 52.627,56.256 on Mechanical 4
52.627,56.256 to 60.378,56.256 on Mechanical 4
68.129,56.256 to 60.378,56.256 on Mechanical 4
75.88,56.256 to 68.129,56.256 on Mechanical 4
75.88,56.256 to 83.631,56.256 on Mechanical 4
87.507,46.255 to 44.876,56.256 on Mechanical 4
83.631,56.256 to 95,75 on Mechanical 4
83.631,56.256 to 95,75 on Mechanical 4
87.507,46.255 to 83.631,56.256 on Mechanical 4
4,42.38 to 7.139,45.518 on Mechanical 4
16,26.877 to 23.1,31.55 on Mechanical 4
16,11.38 to 21.408,17.908 on Mechanical 4
16,26.877 to 31,42.38 on Mechanical 4
16,26.877 to 4,42.38 on Mechanical 4
95,0 to 87.507,7.5 on Mechanical 4
87.507,7.5 to 95,0 on Mechanical 4
31,11.376 to 41,7.5 on Mechanical 4
31,42.38 to 0,75 on Mechanical 4
31,34.629 to 31,42.38 on Mechanical 4
31,26.878 to 31,34.629 on Mechanical 4
31,19.127 to 31,26.878 on Mechanical 4
31,11.376 to 31,19.127 on Mechanical 4
0,0 to 31,11.376 on Mechanical 4
0,0 to 4,42.38 on Mechanical 4
41,7.5 to 87.507,7.5 on Mechanical 4
87.507,7.5 to 87.507,46.255 on Mechanical 4
95,0 to 95,75 on Mechanical 4
0,0 to 95,0 on Mechanical 4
